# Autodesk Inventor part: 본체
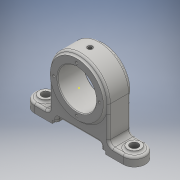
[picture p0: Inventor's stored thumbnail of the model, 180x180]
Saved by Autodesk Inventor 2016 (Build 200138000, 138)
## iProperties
Created: 2019-05
Part Number: 본체
Material: 일반
Document SubType Name: Modeling
Designer: USER
Density: 1 g/cm^3
Appearance: 기본값
Author: USER
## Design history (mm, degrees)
sketch "스케치1"
  geometry: L1 (40, 0)-(40, -48); L2 (40, -48)-(75, -48); L3 (75, -48)-(75, -60); L4 (75, -60)-(36, -60); L5 (36, -60)-(36, -56); L6 (36, -56)-(30, -56); L7 (30, -56)-(30, -50); L8 (30, -50)-(-30, -50); L9 (-30, -50)-(-30, -56); L10 (-30, -56)-(-36, -56); L11 (-36, -56)-(-36, -60); L12 (-36, -60)-(-75, -60); L13 (-75, -60)-(-75, -48); L14 (-75, -48)-(-40, -48); L15 (-40, -48)-(-40, 0); A1 r 40 centre (0, 0) between (40, 0) and (-40, 0); 1 further point
  constraints: 30 end point, 9 perpendicular, 6 point on line, 2 point on circle, 2 tangent, 1 centre point, 1 coincident, 1 horizontal, 1 vertical
  dimensions: "d0" = 80 diameter of A1; "d1" = 72 distance between parallel lines of L11 L5; "d2" = 60 distance between parallel lines of L9 L7; "d3" = 12 distance between parallel lines of L4 L2; "d4" = 4 distance between parallel lines of L4 L6; "d5" = 10 distance between parallel lines of L4 L8; "d6" = 60 distance from line of L4 point (0, 0); "d8" = 30 distance from line of point (0, 0) L7; "d9" = 75 distance from line of point (0, 0) L3; "d10" = 75 distance from line of point (0, 0) L13; "d11" = 48 distance of L14.end L15.end; "d12" = 36 distance from line of point (0, 0) L11
extrude "돌출1" new body sketch "스케치1" distance "d13" = 30; taper "d14" = 0 deg
sketch "스케치2"
  geometry: C1 r 36 at (0, 0); 1 further point
  constraints: 1 centre point, 1 coincident
  dimensions: "d15" = 72 diameter of C1
extrude "돌출2" join sketch "스케치2" distance "d16" = 3; taper "d17" = 0 deg
sketch "스케치3"
  geometry: C1 r 36 at (0, 0); 1 further point
  constraints: 1 centre point, 1 coincident
  dimensions: "d18" = 72 diameter of C1
extrude "돌출3" join sketch "스케치3" distance "d19" = 3; taper "d20" = 0 deg
sketch "스케치4"
  geometry: C1 r 26 at (0, 0); 1 further point
  constraints: 1 centre point, 1 coincident
  dimensions: "d21" = 52 diameter of C1
extrude "돌출4" cut sketch "스케치4" distance "d22" = 100; taper "d23" = 0 deg
sketch "스케치5" dims "d32" = 10
  geometry: L1 (39, 30)-(0, 30) reference; C1 r 9 at (15, 15); C2 r 9 at (135, 15); 1 further point
  constraints: 2 centre point, 1 horizontal, 2 other
  dimensions: "d24" = 60 horizontal distance of point (75, 0) C1.centre; "d25" = 15 distance from line of C1.centre L1; "d26" = 18 diameter of C1; "d29" = 120 distance of C1.centre C2.centre
extrude "돌출5" join sketch "스케치5" distance "d34" = 3; taper "d35" = 0 deg
sketch "스케치6"
  geometry: C1 r 9 at (0, 0) reference; C2 r 5.5 at (0, 0); 1 further point
  constraints: 1 centre point, 1 coincident
  dimensions: "d36" = 11 diameter of C2
extrude "돌출6" cut sketch "스케치6" distance "d37" = 50; taper "d38" = 0 deg
sketch "스케치7"
  geometry: 2 further points
  constraints: 1 vertical alignment
  dimensions: "d42" = 31 distance of point (0, 0) point (0, 31)
hole "구멍1" sketch "스케치7" at (0, 31) diameter "d43" = 3.242; stored, may be unused: countersink angle "d47" = 90 deg, drill point angle "d49" = 118 deg; dims "d44" = 6, "d45" = 4, "d46" = 2, "d48" = 8
sketch "스케치8"
  geometry: 2 further points
  constraints: 1 vertical alignment
  dimensions: "d53" = 31 distance of point (0, 0) point (0, -31)
hole "구멍2" sketch "스케치8" at (0, -31) diameter "d54" = 3.242; stored, may be unused: countersink angle "d58" = 90 deg, drill point angle "d60" = 118 deg; dims "d55" = 6, "d56" = 4, "d57" = 2, "d59" = 8
node "작업 평면1"
fillet "모깎기1" dims "d64" = 6
fillet "모깎기2" dims "d65" = 3
sketch "스케치10"
  geometry: L1 (40, 0)-(-40, 0) reference; L2 (75, 0)-(75, 30) reference; 4 further points
  constraints: 2 midpoint, 1 horizontal alignment, 1 vertical alignment
hole "구멍3" sketch "스케치10" at (0, 15) diameter "d69" = 4.917; stored, may be unused: countersink angle "d73" = 90 deg, drill point angle "d75" = 118 deg; dims "d70" = 8, "d71" = 7, "d72" = 1, "d74" = 10
sketch "스케치11"
  geometry: C1 r 1.5 at (0, 26); 2 further points
  constraints: 2 vertical alignment, 1 centre point, 1 other
  dimensions: "d76" = 3 diameter of C1
extrude "돌출7" cut sketch "스케치11" distance "d77" = 100; taper "d78" = 0 deg
sketch "스케치17"
  geometry: 1 further point
fillet "모깎기4" dims "d80" = 3
fillet "모깎기5" dims "d81" = 3
fillet "모깎기6" dims "d82" = 3
sketch "스케치18"
  geometry: L1 (30, 56)-(30, 53) reference; L2 (27, 50)-(-27, 50) reference; 2 further points
  constraints: 1 other
  dimensions: "d84" = 30 distance from line of L1 point (0, 43); "d85" = 7 distance from line of L2 point (0, 43)
feature "엠보싱1" sketch "스케치18" dims "d86" = 0.5, "d87" = 0
fillet "모깎기8" dims "d88" = 15
fillet "모깎기9" dims "d89" = 3
sketch "스케치19"
  geometry: C1 r 2.458 at (0, 15) reference; C2 r 1 at (0, 15); 1 further point
  constraints: 1 centre point, 1 coincident
  dimensions: "d90" = 2 diameter of C2
extrude "돌출8" cut sketch "스케치19" stored distance "d91" = 50; taper "d92" = 0 deg
chamfer "모따기2" distance "d93" = 1; stored, may be unused: second distance "d94" = 2, angle "d95" = 45 deg
sketch "스케치20"
  geometry: 1 further point
node "솔리드1"
pattern_linear "직사각형 패턴1" dims "d41" = 120
pattern_circular "원형 패턴1" dims angle "d51" = 360 deg
pattern_circular "원형 패턴2" dims angle "d62" = 360 deg
